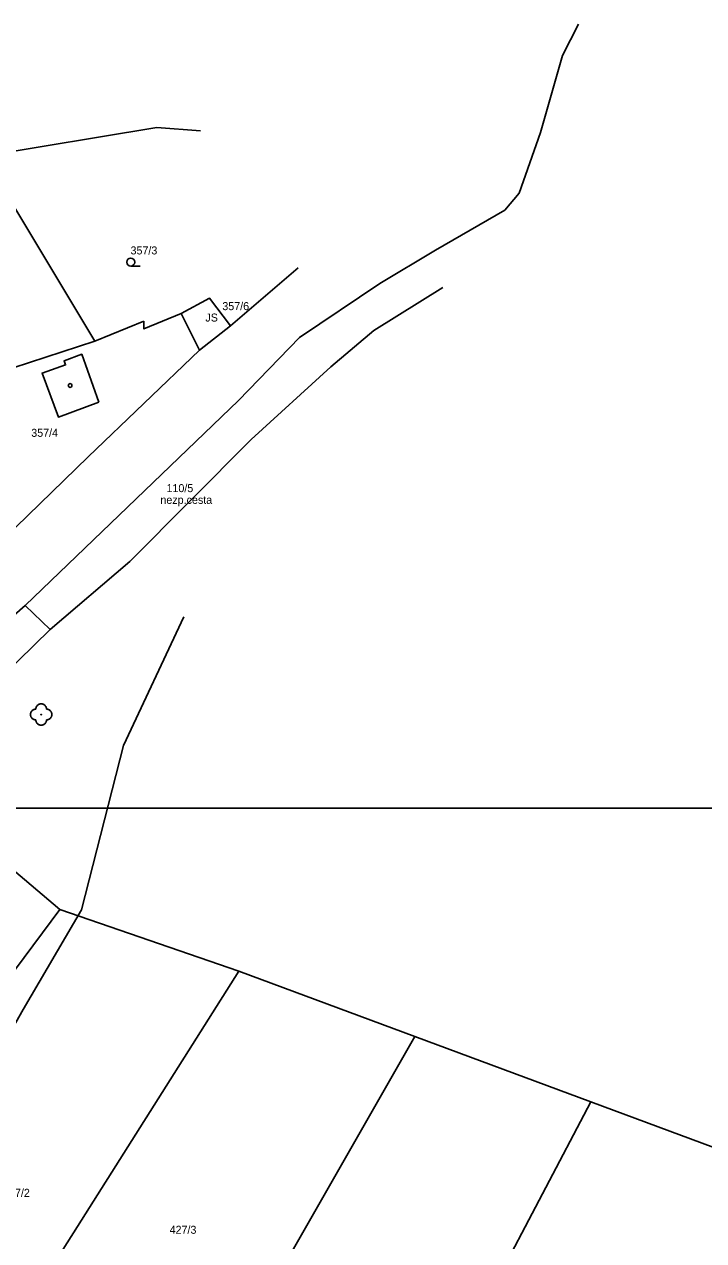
# Model space of a CAD drawing. Extents: x -836615 to -835459, y -1070675 to -1070205.
# Drawn here: x -836456.3 to -836392.7, y -1070319.2 to -1070205.2 of the extents above; entities that cross this region are included whole.
import ezdxf

# ---------------------------------------------------------------- set-up
doc = ezdxf.new("R2010")
doc.units = 0
for name, color, linetype in [('BodPole_body', 7, 'Continuous'), ('Budovy_hranice', 7, 'Continuous'), ('Budovy_kody', 7, 'Continuous'), ('Doprava_hranice', 7, 'Continuous'), ('Doprava_kody', 7, 'Continuous'), ('OstPloch_hranice', 7, 'Continuous'), ('OstPloch_kody', 7, 'Continuous'), ('RuianPar_popis', 7, 'Continuous'), ('Stavby_hr_stav', 7, 'Continuous'), ('Stavby_kody', 7, 'Continuous'), ('Stavby_linie', 7, 'Continuous'), ('Zelen_body', 7, 'Continuous')]:
    doc.layers.add(name, color=color, linetype=linetype)

msp = doc.modelspace()

# ---------------------------------------------------------------- linework, layer by layer
at = {"layer": 'BodPole_body'}
msp.add_lwpolyline([(-836503.12, -1070278.67), (-836206.12, -1070278.67), (-836206.12, -1070488.67), (-836503.12, -1070488.67)], close=True, dxfattribs=at)
at = {"layer": 'Budovy_hranice'}
msp.add_lwpolyline([(-836449.34, -1070240.62), (-836453.11, -1070242.03), (-836454.65, -1070237.91), (-836452.45, -1070237.14), (-836452.58, -1070236.76), (-836450.93, -1070236.14), (-836449.34, -1070240.62)], dxfattribs=at)
at = {"layer": 'Budovy_kody'}
msp.add_line((-836452.98, -1070288.18), (-836436.21, -1070293.95), dxfattribs=at)
for points in [[(-836428.56, -1070366.77), (-836395.84, -1070391.08), (-836420.45, -1070375.43), (-836435.19, -1070364.96), (-836454.22, -1070349.64), (-836469.26, -1070337.57), (-836482.9, -1070325.77), (-836486.89, -1070317.46), (-836480.18, -1070324.33), (-836464.23, -1070338.22), (-836436.21, -1070293.95), (-836419.72, -1070300.08)], [(-836403.24, -1070306.2), (-836419.72, -1070300.08), (-836449.21, -1070351.65), (-836433.24, -1070363.34), (-836416.81, -1070332.05)]]:
    msp.add_lwpolyline(points, dxfattribs=at)
msp.add_lwpolyline([(-836403.24, -1070306.2), (-836374.99, -1070316.69), (-836386.28, -1070344.47), (-836399.48, -1070339.1), (-836416.81, -1070332.05)], close=True, dxfattribs=at)
msp.add_circle((-836452.02, -1070239.07), 0.175, dxfattribs=at)
at = {"layer": 'Doprava_hranice'}
for points in [[(-836456.22, -1070259.67), (-836436.24, -1070240.49), (-836430.53, -1070234.56), (-836423.01, -1070229.52), (-836417.79, -1070226.4), (-836411.3, -1070222.63), (-836409.96, -1070221.04), (-836407.94, -1070215.36), (-836405.88, -1070208.14), (-836404.38, -1070205.23)], [(-836417.09, -1070229.89), (-836423.58, -1070233.93), (-836427.6, -1070237.33), (-836435.05, -1070244.12), (-836446.44, -1070255.57), (-836453.89, -1070261.93)], [(-836463.13, -1070260.78), (-836461.66, -1070261.68), (-836460.5, -1070262.24), (-836459.09, -1070262.17), (-836456.22, -1070259.67), (-836453.89, -1070261.93), (-836464.34, -1070272.16), (-836473.79, -1070281.33)]]:
    msp.add_lwpolyline(points, dxfattribs=at)
at = {"layer": 'OstPloch_hranice'}
msp.add_lwpolyline([(-836356.62, -1070406.87), (-836370.19, -1070399.44), (-836385.43, -1070392.2), (-836396.38, -1070386.03), (-836404.41, -1070381.11), (-836409.87, -1070376.61), (-836425.28, -1070363.93), (-836449.03, -1070345.44), (-836455, -1070340), (-836462.64, -1070329.11), (-836464.81, -1070325.47), (-836465.74, -1070321.03), (-836464.89, -1070314.87), (-836461.62, -1070306.74), (-836456.41, -1070297.54), (-836450.95, -1070288.2), (-836447.03, -1070272.79), (-836441.38, -1070260.76)], dxfattribs=at)
at = {"layer": 'OstPloch_kody'}
msp.add_line((-836445.46, -1070227.89), (-836446.34, -1070227.89), dxfattribs=at)
msp.add_ellipse((-836446.34, -1070227.51), major_axis=(0.375, 0), ratio=0.999999, dxfattribs=at)
at = {"layer": 'Stavby_hr_stav'}
msp.add_lwpolyline([(-836441.61, -1070232.32), (-836438.97, -1070230.88), (-836437.01, -1070233.47), (-836439.91, -1070235.75), (-836441.61, -1070232.32)], dxfattribs=at)
at = {"layer": 'Stavby_linie'}
for p, q in [((-836434.82, -1070231.6), (-836430.66, -1070228.05)), ((-836434.82, -1070231.6), (-836437.01, -1070233.47)), ((-836449.69, -1070234.92), (-836445.12, -1070233.05)), ((-836464.85, -1070239.86), (-836449.69, -1070234.92))]:
    msp.add_line(p, q, dxfattribs=at)
for points in [[(-836439.81, -1070215.21), (-836443.91, -1070214.91), (-836460.13, -1070217.59), (-836449.69, -1070234.92)], [(-836445.12, -1070233.05), (-836445.11, -1070233.77), (-836441.61, -1070232.32)], [(-836460.54, -1070255.66), (-836450.32, -1070245.76), (-836439.91, -1070235.75)], [(-836483.95, -1070318.68), (-836480.18, -1070324.33), (-836477.38, -1070322.05), (-836462.13, -1070300.43), (-836452.98, -1070288.18), (-836458.36, -1070283.6)]]:
    msp.add_lwpolyline(points, dxfattribs=at)
at = {"layer": 'Zelen_body'}
msp.add_line((-836454.73, -1070269.9), (-836454.73, -1070269.9), dxfattribs=at)
for points in [[(-836455.23, -1070270.4), (-836455.28, -1070270.4), (-836455.33, -1070270.39), (-836455.38, -1070270.38), (-836455.43, -1070270.36), (-836455.47, -1070270.34), (-836455.52, -1070270.31), (-836455.56, -1070270.27), (-836455.6, -1070270.23), (-836455.64, -1070270.19), (-836455.67, -1070270.14), (-836455.69, -1070270.1), (-836455.71, -1070270.05), (-836455.72, -1070270), (-836455.73, -1070269.95), (-836455.73, -1070269.9), (-836455.73, -1070269.85), (-836455.72, -1070269.8), (-836455.71, -1070269.75), (-836455.69, -1070269.7), (-836455.67, -1070269.66), (-836455.64, -1070269.61), (-836455.6, -1070269.57), (-836455.56, -1070269.53), (-836455.52, -1070269.49), (-836455.47, -1070269.46), (-836455.43, -1070269.44), (-836455.38, -1070269.42), (-836455.33, -1070269.41), (-836455.28, -1070269.4), (-836455.23, -1070269.4)], [(-836455.23, -1070269.4), (-836455.23, -1070269.35), (-836455.22, -1070269.3), (-836455.21, -1070269.25), (-836455.19, -1070269.2), (-836455.17, -1070269.16), (-836455.14, -1070269.11), (-836455.1, -1070269.07), (-836455.06, -1070269.03), (-836455.02, -1070268.99), (-836454.97, -1070268.96), (-836454.93, -1070268.94), (-836454.88, -1070268.92), (-836454.83, -1070268.91), (-836454.78, -1070268.9), (-836454.73, -1070268.9), (-836454.68, -1070268.9), (-836454.63, -1070268.91), (-836454.58, -1070268.92), (-836454.53, -1070268.94), (-836454.49, -1070268.96), (-836454.44, -1070268.99), (-836454.4, -1070269.03), (-836454.36, -1070269.07), (-836454.32, -1070269.11), (-836454.29, -1070269.16), (-836454.27, -1070269.2), (-836454.25, -1070269.25), (-836454.24, -1070269.3), (-836454.23, -1070269.35), (-836454.23, -1070269.4)], [(-836454.23, -1070269.4), (-836454.18, -1070269.4), (-836454.13, -1070269.41), (-836454.08, -1070269.42), (-836454.03, -1070269.44), (-836453.99, -1070269.46), (-836453.94, -1070269.49), (-836453.9, -1070269.53), (-836453.86, -1070269.57), (-836453.82, -1070269.61), (-836453.79, -1070269.66), (-836453.77, -1070269.7), (-836453.75, -1070269.75), (-836453.74, -1070269.8), (-836453.73, -1070269.85), (-836453.73, -1070269.9), (-836453.73, -1070269.95), (-836453.74, -1070270), (-836453.75, -1070270.05), (-836453.77, -1070270.1), (-836453.79, -1070270.14), (-836453.82, -1070270.19), (-836453.86, -1070270.23), (-836453.9, -1070270.27), (-836453.94, -1070270.31), (-836453.99, -1070270.34), (-836454.03, -1070270.36), (-836454.08, -1070270.38), (-836454.13, -1070270.39), (-836454.18, -1070270.4), (-836454.23, -1070270.4)], [(-836454.23, -1070270.4), (-836454.23, -1070270.45), (-836454.24, -1070270.5), (-836454.25, -1070270.55), (-836454.27, -1070270.6), (-836454.29, -1070270.64), (-836454.32, -1070270.69), (-836454.36, -1070270.73), (-836454.4, -1070270.77), (-836454.44, -1070270.81), (-836454.49, -1070270.84), (-836454.53, -1070270.86), (-836454.58, -1070270.88), (-836454.63, -1070270.89), (-836454.68, -1070270.9), (-836454.73, -1070270.9), (-836454.78, -1070270.9), (-836454.83, -1070270.89), (-836454.88, -1070270.88), (-836454.93, -1070270.86), (-836454.97, -1070270.84), (-836455.02, -1070270.81), (-836455.06, -1070270.77), (-836455.1, -1070270.73), (-836455.14, -1070270.69), (-836455.17, -1070270.64), (-836455.19, -1070270.6), (-836455.21, -1070270.55), (-836455.22, -1070270.5), (-836455.23, -1070270.45), (-836455.23, -1070270.4)]]:
    msp.add_lwpolyline(points, dxfattribs=at)
msp.add_ellipse((-836454.73, -1070269.9), major_axis=(0.025, 0), ratio=0.999997, dxfattribs=at)

# ---------------------------------------------------------------- texts
at = {"layer": 'Doprava_kody'}
msp.add_text('nezp.cesta', height=0.75, dxfattribs=at).set_placement((-836443.56, -1070250.16))
at = {"layer": 'RuianPar_popis'}
for s, p in [('357/3', (-836446.36, -1070226.79)), ('357/6', (-836437.76, -1070232.01)), ('357/4', (-836455.66, -1070243.88)), ('110/5', (-836442.99, -1070249.06)), ('427/2', (-836458.3, -1070315.09)), ('427/3', (-836442.7, -1070318.55))]:
    msp.add_text(s, height=0.75, dxfattribs=at).set_placement(p)
at = {"layer": 'Stavby_kody'}
msp.add_text('JS', height=0.75, dxfattribs=at).set_placement((-836439.35, -1070233.08))

doc.saveas('drawing.dxf')
